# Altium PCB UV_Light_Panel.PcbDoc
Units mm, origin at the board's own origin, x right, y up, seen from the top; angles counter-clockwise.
Board outline 9 x 19.6 mm, 2 copper layers (Top Layer, Bottom Layer), stack 1.026 mm thick; 5 components, 2 nets, 12 pads, 0 vias.
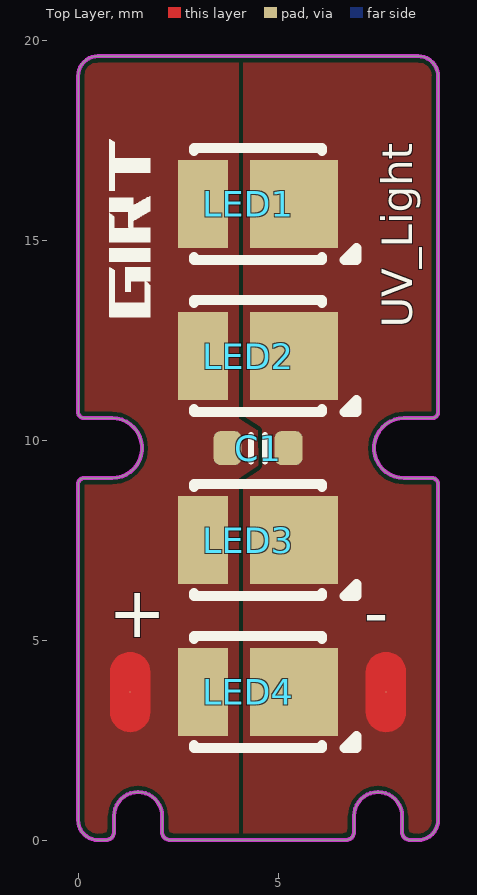
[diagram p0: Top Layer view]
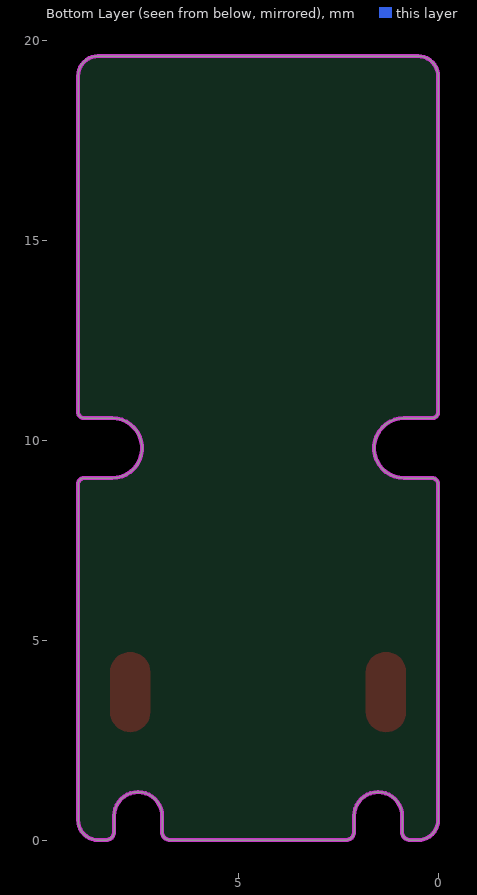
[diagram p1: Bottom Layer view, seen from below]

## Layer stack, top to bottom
Top Solder: solder mask 0.0127, Solder Resist, Dk 3.3
Top Layer: signal copper 0.0178
Dielectric1: core 0.9906, Core-042, Dk 4.6
Bottom Layer: signal copper 0.0178
Bottom Solder: solder mask 0.0127, Solder Resist, Dk 3.3

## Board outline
0.5,0 0.7,0 ccw(c0.7,0.2) 0.9,0.2 0.9,0.6 cw(c1.5,0.6) 1.5,1.2 cw(c1.5,0.6) 2.1,0.6 2.1,0.2 ccw(c2.3,0.2) 2.3,0 6.7,0 ccw(c6.7,0.2) 6.9,0.2 6.9,0.6 cw(c7.5,0.6) 7.5,1.2 cw(c7.5,0.6) 8.1,0.6 8.1,0.2 ccw(c8.3,0.2) 8.3,0 8.5,0 ccw(c8.5,0.5) 9,0.5 9,8.9 ccw(c8.85,8.9) 8.85,9.05 8.15,9.05 cw(c8.15,9.8) 8.15,10.55 8.85,10.55 ccw(c8.85,10.7) 9,10.7 9,19.1 ccw(c8.5,19.1) 8.5,19.6 0.5,19.6 ccw(c0.5,19.1) 0,19.1 0,10.7 ccw(c0.15,10.7) 0.15,10.55 0.85,10.55 cw(c0.85,9.8) 0.85,9.05 0.15,9.05 ccw(c0.15,8.9) 0,8.9 0,0.5 ccw(c0.5,0.5)

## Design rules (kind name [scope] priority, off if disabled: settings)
Clearance [All] p1: gap=0.102 ignorepadtopadclearanceinfootprint=TRUE except(0: Arc-Hole Track-Hole SMDPad-Hole THPad-Hole Via-Hole Fill-Hole Poly-Hole Region-Hole Text-Hole)
ComponentClearance [All] p1: gap=0 collisioncheckmode=3 verticalgap=0 showdistances=FALSE
DiffPairsRouting [All] p1: maxlimit=0.229 minlimit=0.102 mostfreqgap=0.102 toplayer_minwidth=0.102 toplayer_maxwidth=0.381 toplayer_prefwidth=0.381 bottomlayer_minwidth=0.102 bottomlayer_maxwidth=0.381 bottomlayer_prefwidth=0.381 maxuncoupledlength=12.7
FanoutControl Fanout_BGA [All] p1: bgadir=Out bgaviamode=Centered fanoutstyle=Auto fanoutdirection=Alternating viagrid=0.025 // Fanout_BGA (Default Rule)
Height [All] p1: minheight=0 maxheight=254 prefheight=12.7
HoleSize [All] p1: absolutevalues=TRUE maxlimit=254 minlimit=0.203 maxpercent=80.000 minpercent=20.000
MinimumSolderMaskSliver [All] p1 off: minsoldermaskwidth=0.051
PlaneClearance [All] p1: clearance=0.203
PlaneConnect [All] p1: planeconnectstyle=Direct reliefexpansion=0.508 reliefentries=4 reliefconductorwidth=0.254 reliefairgap=0.254
PolygonConnect [All] p1: connectstyle=Direct reliefconductorwidth=0.254 reliefentries=4 polygonreliefangle="90 Angle" airgapwidth=0.254
RoutingVias [All] p1: holewidth=0.203 width=0.406 viastyle="Through Hole" minholewidth=0.152 minwidth=0.305 maxholewidth=0.711 maxwidth=1.27
SilkToSilkClearance [All] p1: silktosilkclearance=0
SilkToSolderMaskClearance [IsPad] p1: minsilkscreentomaskgap=0 clearancetoexposedcopper=TRUE
SolderMaskExpansion [All] p1: expansion=0.076 istentingtop=FALSE
Width GND [(InNet('AGND') OR InNet('GND'))] p1: maxlimit=1.27 minlimit=0.102 preferedwidth=0.254
Width VCC [(InNet('VDD_SYS_3.3V') OR InNet('VDD_AV_3.3V') OR InNet('VDD_5V') OR InNet('VDD1V2-SYS') OR InNet('VDD1V1-EPHY') OR InNet('VDD-CPUX') OR InNet('VDD-CPUS') OR InNet('VDD-CPUFB') OR InNet('VCC-DRAM'))] p2: maxlimit=1.27 minlimit=0.102 preferedwidth=0.254
Width [All] p3: maxlimit=254 minlimit=0.254 preferedwidth=0.254
20 further rules are at their usual default settings.

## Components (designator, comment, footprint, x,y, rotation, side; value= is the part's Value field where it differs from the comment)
C1 "CL10B104KB8NNNC" "C 0603(1608)100_L" 4.5,9.8 r0 top locked value=100nF
LED1 "FZ-2835UPC60A08 395" "LED 2835" 4.26,15.9 r180 top locked
LED2 "FZ-2835UPC60A08 395" "LED 2835" 4.26,12.1 r180 top locked
LED3 "FZ-2835UPC60A08 395" "LED 2835" 4.26,7.5 r180 top locked
LED4 "FZ-2835UPC60A08 395" "LED 2835" 4.26,3.7 r180 top locked

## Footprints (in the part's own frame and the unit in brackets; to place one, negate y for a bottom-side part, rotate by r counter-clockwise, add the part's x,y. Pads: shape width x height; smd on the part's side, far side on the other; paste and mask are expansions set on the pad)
"C 0603(1608)100_L" [mm] "长度1.6mm，宽度为0.8mm，高度0.8mm"
  rrect50% 0.7x0.849 smd: 1(-0.762,0) 2(0.762,0)
  silkscreen extent -0.18,-0.33 0.18,0.33, body extent -0.8,-0.41 0.8,0.41, height 0.81
"LED 2835" [mm]
  rect 1.25x2.2 smd mask+0.051: 1(1.138,0)
  rect 2.2x2.2 smd mask+0.051: 2(-1.138,0)
  silkscreen extent -2.7,-1.4 1.36,1.4, body extent -1.9,-1.4 1.4,1.4, height 0.83

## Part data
C1: library part CMP-001-00085-2, "Multi Layer Ceramic Capacitor (MLCC) / Cap Ceramic 0.1uF 50V X7R 10% Pad SMD 0603 125¡ãC T/R", Capacitance=100nF, Case Code (Imperial)=0603, Case Code (Metric)=1608, Dielectric=X7R, Max Operating Temperature=125°C, Min Operating Temperature=-55°C, Package Quantity=1, Tolerance=10%, Voltage=50V
LED1 LED2 LED3 LED4: library part CMP-007-00089-2, "PLCC 2835 Purple LED 395NM", Case/Package=SMD, Colour=UV, Forward Current=60mA, Forward Voltage=3.4V, Max Power Dissipation=200mW, Reverse Current Max(VR{}5V)=10uA

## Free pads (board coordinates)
  round 0.025 smd: 1(1.304,3.7) 1(7.696,3.7)

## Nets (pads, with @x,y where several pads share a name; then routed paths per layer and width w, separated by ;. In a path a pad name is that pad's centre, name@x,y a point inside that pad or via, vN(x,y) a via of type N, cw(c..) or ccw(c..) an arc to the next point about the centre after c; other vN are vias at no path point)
GND: C1.2 LED1.2 LED2.2 LED3.2 LED4.2 pad.1@7.696,3.7
VCC: C1.1 LED1.1 LED2.1 LED3.1 LED4.1 pad.1@1.304,3.7

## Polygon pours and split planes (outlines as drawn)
VCC on Top Layer "NONET_L01_P-001" (solid, remove dead copper, pour order 1): 4.013,0 4.013,9.038 4.502,9.363 4.498,10.24 4.013,10.543 4.013,19.6 0,19.6 0,0
GND on Top Layer "NONET_L01_P-001" (solid, remove dead copper, pour order 0): 4.032,0 4.025,9.032 4.5,9.325 4.5,10.252 4.026,10.515 4.032,19.6 9,19.6 9,0

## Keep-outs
Keep-Out Layer:
  the board outline again, w0.102

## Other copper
Top Layer:
  region net GND: 7.196,3.2 ccw(c7.696,3.2) 7.696,2.7 ccw(c7.696,3.2) 8.196,3.2 8.196,4.2 ccw(c7.696,4.2) 7.696,4.7 ccw(c7.696,4.2) 7.196,4.2
  region net VCC: 0.804,3.2 ccw(c1.304,3.2) 1.304,2.7 ccw(c1.304,3.2) 1.804,3.2 1.804,4.2 ccw(c1.304,4.2) 1.304,4.7 ccw(c1.304,4.2) 0.804,4.2

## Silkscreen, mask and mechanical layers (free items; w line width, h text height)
Top Overlay:
  drawing of 4 lines, arcs and shapes, not listed
  text "UV_Light" at 8.349,12.811 h0.76 r90
  text "+" at 0.751,5.069 h1.27
  text "-" at 7.144,5.069 h1.27
Board:
  the board outline again, w0.102
Drill Drawing:
  lines w0.025: 100.625,3.305 102.908,5.588 105.956,8.636 109.004,11.684 112.052,14.732 113.576,16.256 ; 100.625,4.829 101.384,5.588 104.432,8.636 107.48,11.684 110.528,14.732 113.576,17.78 ; 100.625,6.353 102.908,8.636 105.956,11.684 109.004,14.732 112.052,17.78 113.576,19.304 ; 100.625,7.877 101.384,8.636 104.432,11.684 107.48,14.732 110.528,17.78 113.576,20.828 ; 100.625,9.401 102.908,11.684 105.956,14.732 109.004,17.78 112.052,20.828 113.576,22.352 ; 100.625,10.925 101.384,11.684 104.432,14.732 107.48,17.78 110.528,20.828 113.576,23.876 ; 100.625,12.449 102.908,14.732 105.956,17.78 109.004,20.828 112.052,23.876 ; 100.625,13.973 101.384,14.732 104.432,17.78 107.48,20.828 110.528,23.876 ; 100.625,15.497 102.908,17.78 105.956,20.828 109.004,23.876 ; 100.625,17.021 101.384,17.78 104.432,20.828 107.48,23.876 ; 100.625,18.545 102.908,20.828 105.956,23.876 ; 100.625,20.069 101.384,20.828 104.432,23.876 ; 100.625,21.593 102.908,23.876 ; 100.625,23.117 101.384,23.876 ; 101.384,2.54 104.432,5.588 107.48,8.636 110.528,11.684 113.576,14.732 ; 102.908,2.54 105.956,5.588 109.004,8.636 112.052,11.684 113.576,13.208 ; 104.432,2.54 107.48,5.588 110.528,8.636 113.576,11.684 ; 105.956,2.54 109.004,5.588 112.052,8.636 113.576,10.16 ; 107.48,2.54 110.528,5.588 113.576,8.636 ; 109.004,2.54 112.052,5.588 113.576,7.112 ; 110.528,2.54 113.576,5.588 ; 112.052,2.54 113.576,4.064
  lines w0.381: 13.779,5.588 24.191,5.588 47.807,5.588 69.645,5.588 86.151,5.588 100.625,5.588 113.576,5.588 ; 13.779,8.636 24.191,8.636 47.807,8.636 69.645,8.636 86.151,8.636 100.625,8.636 113.576,8.636 ; 13.779,11.684 24.191,11.684 47.807,11.684 69.645,11.684 86.151,11.684 100.625,11.684 113.576,11.684 ; 13.779,14.732 24.191,14.732 47.807,14.732 69.645,14.732 86.151,14.732 100.625,14.732 113.576,14.732 ; 13.779,17.78 24.191,17.78 47.807,17.78 69.645,17.78 86.151,17.78 100.625,17.78 113.576,17.78 ; 13.779,20.828 24.191,20.828 47.807,20.828 69.645,20.828 86.151,20.828 100.625,20.828 113.576,20.828 ; 13.779,23.876 113.576,23.876 ; 24.191,26.924 24.191,2.54 ; 47.807,26.924 47.807,2.54 ; 69.645,26.924 69.645,2.54 ; 86.151,26.924 86.151,2.54 ; 100.625,26.924 100.625,2.54 ; 24.191,2.54 47.807,2.54 ; 24.191,2.54 13.779,2.54 13.779,26.924 113.576,26.924 113.576,2.54 100.625,2.54 ; 47.807,2.54 69.645,2.54 ; 69.645,2.54 86.151,2.54 ; 86.151,2.54 100.625,2.54
  text "Layer" at 15.557,24.638 h1.52
  text "Name" at 25.969,24.638 h1.52
  text "Material" at 49.585,24.638 h1.52
  text "Thickness" at 71.423,24.638 h1.52
  text "Constant" at 87.929,24.638 h1.52
  text "Rigid" at 102.403,24.638 h1.52
  text "Top Overlay" at 25.969,21.59 h1.52
  text "Top Solder" at 25.969,18.542 h1.52
  text "Solder Resist" at 49.585,18.542 h1.52
  text "0.013mm" at 71.423,18.542 h1.52
  text "3.3" at 87.929,18.542 h1.52
  text "1" at 15.557,15.494 h1.52
  text "Top Layer" at 25.969,15.494 h1.52
  text "0.018mm" at 71.423,15.494 h1.52
  text "Dielectric1" at 25.969,12.446 h1.52
  text "Core-042" at 49.585,12.446 h1.52
  text "0.991mm" at 71.423,12.446 h1.52
  text "4.6" at 87.929,12.446 h1.52
  text "2" at 15.557,9.398 h1.52
  text "Bottom Layer" at 25.969,9.398 h1.52
  text "0.018mm" at 71.423,9.398 h1.52
  text "Bottom Solder" at 25.969,6.35 h1.52
  text "Solder Resist" at 49.585,6.35 h1.52
  text "0.013mm" at 71.423,6.35 h1.52
  text "3.3" at 87.929,6.35 h1.52
  text "Bottom Overlay" at 25.969,3.302 h1.52
  text "Total board thickness:" at 15.557,0.254 h1.52
  text "1.052mm" at 71.423,0.254 h1.52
